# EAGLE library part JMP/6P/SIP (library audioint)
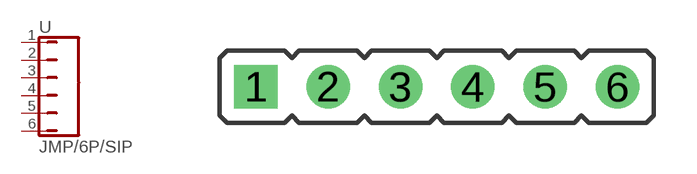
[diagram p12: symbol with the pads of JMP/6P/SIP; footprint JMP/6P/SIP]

Designator prefix -

## JMP/6P/SIP  [JMP/6P/SIP]
1  1  pas
2  2  pas
3  3  pas
4  4  pas
5  5  pas
6  6  pas

## Footprint JMP/6P/SIP (pad centres in mm)
drill 0.914 pad 1.524 square: 1 -6.35,0
drill 0.914 pad 1.524 round: 2 -3.81,0; 3 -1.27,0; 4 1.27,0; 5 3.81,0; 6 6.35,0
